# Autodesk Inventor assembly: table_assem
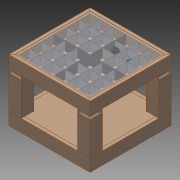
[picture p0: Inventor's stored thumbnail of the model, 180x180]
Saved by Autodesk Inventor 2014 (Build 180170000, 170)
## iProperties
Created: 2014-05
Part Number: table_assem
Document SubType Name: Assembly
Designer: t_emanb
Author: t_emanb
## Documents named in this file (12)
- C:\Users\t_emanb\Documents\Disco Panel Table\Version 1\table_assem.iam
- C:\Users\t_emanb\Documents\Disco Panel Table\Version 1\top_frame.ipt
- C:\Users\t_emanb\Documents\Disco Panel Table\Version 1\top_acrylic.ipt
- C:\Users\t_emanb\Documents\Disco Panel Table\Version 1\base_frame.ipt
- C:\Users\t_emanb\Documents\Disco Panel Table\Version 1\base_plywood.ipt
- C:\Users\t_emanb\Documents\Disco Panel Table\Version 1\leg_assem.iam
- C:\Users\t_emanb\Documents\Disco Panel Table\Version 1\top_support.ipt
- C:\Users\t_emanb\Documents\Disco Panel Table\Version 1\top_electray.ipt
- C:\Users\t_emanb\Documents\Disco Panel Table\Version 1\dividers_assem.iam
- C:\Users\t_emanb\Documents\Disco Panel Table\Version 1\base_triangles.ipt
- C:\Users\t_emanb\Documents\Stock CAD\ArduinoMega.ipt
- C:\Users\t_emanb\Documents\Stock CAD\8AAbatterypack.ipt
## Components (23 placed, 11 different names)
1. top_frame:1 — Flush:1, Mate:3, Mate:4, Mate:6, Flush:8, Mate:59
2. top_frame:2 — Mate:1, Flush:1, Flush:3, Mate:2, Mate:5, Mate:8, Mate:56
3. top_frame:3 — Flush:3, Mate:2, Mate:3, Flush:25, Mate:58
4. top_frame:4 — Mate:4, Mate:5, Mate:6, Mate:7, Flush:7, Mate:19, Mate:22, Mate:41, Mate:55
5. top_acrylic:1 — Mate:1, Mate:7, Mate:8, Mate:41
6. base_frame:1 — Flush:5, Flush:6, Mate:9, Mate:11, Mate:14, Mate:15, Mate:17, Flush:15
7. base_frame:2 — Flush:4, Mate:9, Mate:10, Flush:17, Flush:19
8. base_frame:3 — Flush:4, Flush:5, Mate:10, Mate:12, Mate:13, Flush:7, Flush:13, Flush:16
9. base_frame:4 — Flush:6, Mate:11, Mate:12, Mate:13, Mate:14, Mate:16, Flush:8, Flush:12, Flush:14, Mate:43
10. base_plywood:1 — Mate:15, Mate:16, Mate:17, Mate:18, Mate:42
11. leg_assem:1 [sub-assembly] — Flush:9, Flush:14, Flush:15, Mate:21
12. leg_assem:2 [sub-assembly] — Flush:10, Flush:11, Flush:16, Flush:17
13. leg_assem:3 [sub-assembly] — Flush:11, Mate:18, Flush:19, Flush:25
14. leg_assem:4 [sub-assembly] — Flush:9, Flush:10, Flush:12, Flush:13, Mate:22
15. top_support:1 — Mate:19, Mate:21, Flush:21, Mate:53, Mate:54, Mate:55
16. top_electray:1 — Mate:50, Mate:51, Mate:52, Mate:54, Mate:57
17. top_support:2 — Flush:23, Mate:28, Mate:29, Mate:31, Mate:32, Mate:51
18. top_support:3 — Flush:22, Flush:23, Mate:31, Mate:32, Mate:50, Mate:53, Mate:56
19. top_support:4 — Flush:21, Flush:22, Mate:28, Mate:29, Mate:52
20. dividers_assem:1 [sub-assembly] — Angle:1, Mate:57, Mate:58, Mate:59
21. base_triangles:4 — Mate:42, Mate:43
22. ArduinoMega:1 — Flush:24, Angle:1
23. 8AAbatterypack:1 — Flush:24
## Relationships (61: Mate 38, Flush 22, Angle 1)
- Mate:1: top_frame:2 ↔ top_acrylic:1
- Flush:1: top_frame:1 ↔ top_frame:2
- Flush:3: top_frame:2 ↔ top_frame:3
- Mate:2: top_frame:2 ↔ top_frame:3
- Mate:3: top_frame:1 ↔ top_frame:3
- Mate:4: top_frame:1 ↔ top_frame:4
- Mate:5: top_frame:2 ↔ top_frame:4
- Mate:6: top_frame:1 ↔ top_frame:4
- Mate:7: top_frame:4 ↔ top_acrylic:1
- Mate:8: top_frame:2 ↔ top_acrylic:1
- Flush:4: base_frame:2 ↔ base_frame:3
- Flush:5: base_frame:1 ↔ base_frame:3
- Flush:6: base_frame:1 ↔ base_frame:4
- Mate:9: base_frame:1 ↔ base_frame:2
- Mate:10: base_frame:2 ↔ base_frame:3
- Mate:11: base_frame:1 ↔ base_frame:4
- Mate:12: base_frame:3 ↔ base_frame:4
- Mate:13: base_frame:3 ↔ base_frame:4
- Mate:14: base_frame:1 ↔ base_frame:4
- Mate:15: base_frame:1 ↔ base_plywood:1
- Mate:16: base_frame:4 ↔ base_plywood:1
- Mate:17: base_frame:1 ↔ base_plywood:1
- Flush:7: top_frame:4 ↔ base_frame:3
- Flush:8: top_frame:1 ↔ base_frame:4
- Flush:9: leg_assem:1 ↔ leg_assem:4
- Flush:10: leg_assem:2 ↔ leg_assem:4
- Flush:11: leg_assem:2 ↔ leg_assem:3
- Mate:18: base_plywood:1 ↔ leg_assem:3
- Flush:12: base_frame:4 ↔ leg_assem:4
- Flush:13: base_frame:3 ↔ leg_assem:4
- Flush:14: base_frame:4 ↔ leg_assem:1
- Flush:15: base_frame:1 ↔ leg_assem:1
- Flush:16: base_frame:3 ↔ leg_assem:2
- Flush:17: base_frame:2 ↔ leg_assem:2
- Flush:19: base_frame:2 ↔ leg_assem:3
- Mate:19: top_frame:4 ↔ top_support:1
- Mate:21: leg_assem:1 ↔ top_support:1
- Mate:22: top_frame:4 ↔ leg_assem:4
- Flush:21: top_support:1 ↔ top_support:4
- Flush:22: top_support:3 ↔ top_support:4
- Flush:23: top_support:2 ↔ top_support:3
- Mate:28: top_support:2 ↔ top_support:4
- Mate:29: top_support:2 ↔ top_support:4
- Mate:31: top_support:2 ↔ top_support:3
- Mate:32: top_support:2 ↔ top_support:3
- Mate:41: top_frame:4 ↔ top_acrylic:1
- Mate:42: base_plywood:1 ↔ base_triangles:4
- Mate:43: base_frame:4 ↔ base_triangles:4
- Flush:24: ArduinoMega:1 ↔ 8AAbatterypack:1
- Angle:1: dividers_assem:1 ↔ ArduinoMega:1
- Mate:50: top_electray:1 ↔ top_support:3
- Mate:51: top_electray:1 ↔ top_support:2
- Mate:52: top_electray:1 ↔ top_support:4
- Mate:53: top_support:1 ↔ top_support:3
- Mate:54: top_support:1 ↔ top_electray:1
- Mate:55: top_frame:4 ↔ top_support:1
- Mate:56: top_frame:2 ↔ top_support:3
- Flush:25: top_frame:3 ↔ leg_assem:3
- Mate:57: top_electray:1 ↔ dividers_assem:1
- Mate:58: top_frame:3 ↔ dividers_assem:1
- Mate:59: top_frame:1 ↔ dividers_assem:1
